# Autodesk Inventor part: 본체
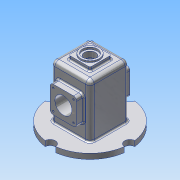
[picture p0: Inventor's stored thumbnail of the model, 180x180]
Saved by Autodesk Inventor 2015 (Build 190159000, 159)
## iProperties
Created: 2018-07
Part Number: 본체
Material: 알루미늄 6061
Document SubType Name: Modeling
Designer: user
Density: 2.7 g/cm^3
Appearance: 알루미늄 - 평지
Author: user
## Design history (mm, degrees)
sketch "스케치1"
  geometry: L1 (-37, -37)-(37, -37); L2 (37, -37)-(37, 37); L3 (37, 37)-(-37, 37); L4 (-37, 37)-(-37, -37); L5 (-37, -37)-(37, 37); L6 (37, -37)-(-37, 37); 1 further point
  constraints: 12 end point, 2 midpoint, 2 parallel, 1 horizontal, 1 perpendicular
  dimensions: "d0" = 74 distance of L3.end L2.end; "d1" = 74 distance of L2.end L1.end
extrude "돌출1" new body sketch "스케치1" stored distance "d2" = 100; taper "d3" = 0 deg
feature "쉘1" dims "d17" = 5
sketch "스케치4"
  geometry: L1 (32, 32)-(32, -32) reference; L2 (32, -32)-(-32, -32) reference; L3 (-32, -32)-(-32, 32) reference; L4 (-32, 32)-(32, 32) reference; C1 r 75 at (0, 0); 1 further point
  constraints: 1 centre point, 1 coincident
  dimensions: "d18" = 150 diameter of C1
extrude "돌출3" join sketch "스케치4" distance "d19" = 10; taper "d20" = 0 deg
sketch "스케치5"
  geometry: L1 (0, 0)-(-75, 0); 1 further point
  constraints: 2 end point, 1 coincident, 1 horizontal, 1 horizontal alignment, 1 other
hole "구멍2" sketch "스케치5" at (-75, 0) diameter "d21" = 20; stored, may be unused: countersink angle "d25" = 90 deg, drill point angle "d27" = 118 deg; dims "d22" = 6, "d23" = 4, "d24" = 2, "d26" = 8
sketch "스케치6"
  geometry: L1 (12, -75)-(62, -75); L2 (62, -75)-(62, -25); L3 (62, -25)-(12, -25); L4 (12, -25)-(12, -75); L5 (12, -75)-(62, -25); L6 (62, -75)-(12, -25); 1 further point
  constraints: 12 end point, 2 midpoint, 2 parallel, 1 horizontal, 1 perpendicular
  dimensions: "d31" = 50 distance of L3.end L2.end; "d32" = 50 distance of L2.end L1.end
extrude "돌출4" join sketch "스케치6" distance "d33" = 13; taper "d34" = 0 deg
sketch "스케치7"
  geometry: L1 (-50, -65)-(-60, -65) reference; L2 (-60, -65)-(-60, -32) reference; L3 (-60, -32)-(45, -32) reference; L4 (45, -32)-(45, 32) reference; L5 (45, 32)-(-60, 32) reference; L6 (-60, 32)-(-60, 65) reference; L7 (-60, 65)-(-50, 65) reference; L8 (-50, 65)-(-50, 37) reference; L9 (-50, 37)-(-25, 37) reference; L10 (-25, 37)-(-25, 50) reference; L11 (-25, 50)-(25, 50) reference; L12 (25, 50)-(25, 37) reference; L13 (25, 37)-(50, 37) reference; L14 (50, 37)-(50, -37) reference; L15 (50, -37)-(-50, -37) reference; L16 (-50, -37)-(-50, -65) reference; L17 (25, 32)-(22.452, 25); L18 (0, 50)-(0, 0); L19 (22.452, 25)-(0, 25); L20 (25, 32)-(0, 32)
  constraints: 8 end point, 3 point on line, 2 midpoint, 1 horizontal, 1 vertical
  dimensions: "d35" = 7 distance between parallel lines of L19 L20; "d36" = 110 deg angle of L5 L17; "d37" = 50 diameter of L17.start L18
revolve "회전1" sketch "스케치7" stored, may be unused: angle "d38" = 90 deg
sketch "스케치8"
  geometry: C1 r 16 at (37, -50); 1 further point
  constraints: 1 centre point, 1 coincident
  dimensions: "d39" = 32 diameter of C1
extrude "돌출5" cut sketch "스케치8" stored distance "d40" = 13; taper "d41" = 0 deg
sketch "스케치9"
  geometry: L1 (-20, -20)-(20, -20); L2 (20, -20)-(20, 20); L3 (20, 20)-(-20, 20); L4 (-20, 20)-(-20, -20); L5 (-20, -20)-(20, 20); L6 (20, -20)-(-20, 20); 1 further point
  constraints: 12 end point, 2 midpoint, 2 parallel, 1 horizontal, 1 perpendicular
  dimensions: "d42" = 40 distance of L3.end L2.end; "d43" = 40 distance of L2.end L1.end
extrude "돌출6" join sketch "스케치9" distance "d44" = 7; taper "d45" = 0 deg
sketch "스케치10"
  geometry: C1 r 17.5 at (0, 0); 1 further point
  constraints: 1 centre point, 1 coincident
  dimensions: "d46" = 35 diameter of C1
extrude "돌출7" join sketch "스케치10" distance "d47" = 3; taper "d48" = 0 deg
sketch "스케치11"
  geometry: C1 r 17.5 at (0, 0) reference; 1 further point
  constraints: 1 coincident
hole "구멍3" sketch "스케치11" at (0, 0) diameter "d49" = 21; stored, may be unused: countersink angle "d53" = 90 deg, drill point angle "d55" = 118 deg; dims "d50" = 6, "d51" = 28, "d52" = 4, "d54" = 8
fillet "모깎기1" dims "d56" = 6
sketch "스케치13"
  geometry: A1 r 6 centre (18, -69) between (12, -69) and (18, -75) reference; A2 r 6 centre (56, -69) between (56, -75) and (62, -69) reference; A3 r 6 centre (56, -31) between (62, -31) and (56, -25) reference; A4 r 6 centre (18, -31) between (18, -25) and (12, -31) reference; 4 further points
  constraints: 4 coincident
hole "구멍4" sketch "스케치13" at (18, -31), (18, -69), (56, -69), (56, -31) diameter "d57" = 3.242; stored, may be unused: countersink angle "d61" = 90 deg, drill point angle "d63" = 118 deg; dims "d58" = 8, "d59" = 28, "d60" = 4, "d62" = 10
fillet "모깎기2" dims "d64" = 3
fillet "모깎기3" dims "d65" = 8
fillet "모깎기4" dims "d66" = 8
fillet "모깎기5" dims "d67" = 3
fillet "모깎기6" dims "d68" = 3
fillet "모깎기7" dims "d69" = 3
fillet "모깎기8" dims "d70" = 3
node "솔리드1"
pattern_circular "원형 패턴2" dims angle "d29" = 360 deg
mirror "대칭1"
mirror "대칭2"
node "절단 모서리 투영1"
